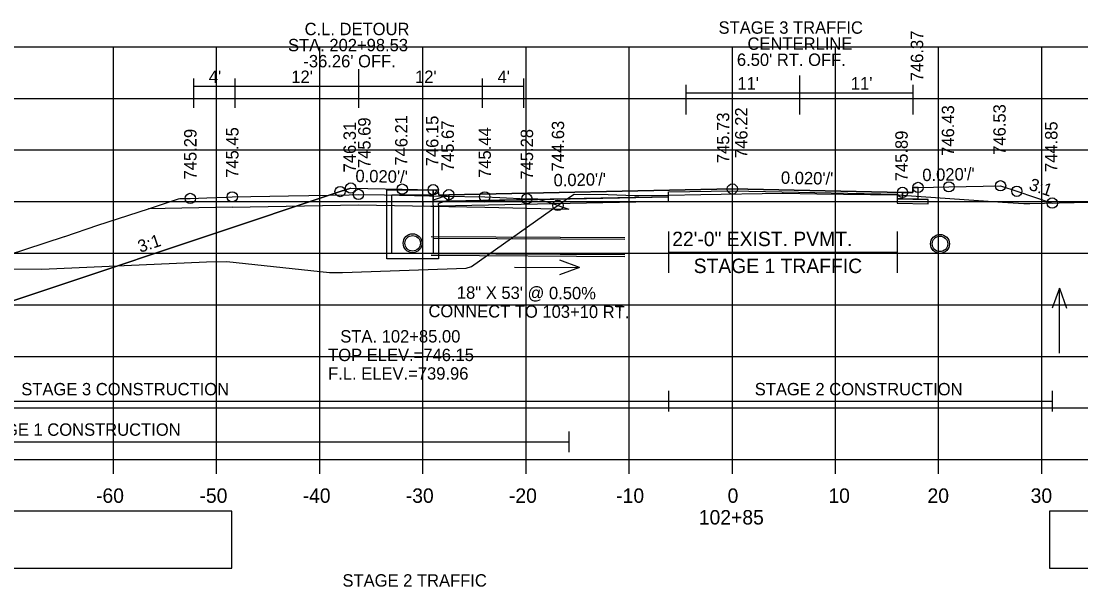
# Model space of a CAD drawing. Extents: x 1202951 to 1376887, y 378065 to 728038.
# Drawn here: x 1376515.7 to 1376618.5, y 378682.8 to 378737.6 of the extents above; entities that cross this region are included whole.
import ezdxf

# ---------------------------------------------------------------- set-up
doc = ezdxf.new("R2010")
doc.units = 0
for name, color, linetype in [('Default', 7, 'Continuous'), ('R_Alt Surface', 7, 'Continuous'), ('R_Axis', 7, 'Continuous'), ('R_Axis Annot', 7, 'Continuous'), ('R_Detour', 7, 'Continuous'), ('R_Detour Annot', 7, 'Continuous'), ('R_Dimension', 7, 'Continuous'), ('R_Exist Surface', 7, 'Continuous'), ('R_Fin Surface', 7, 'Continuous'), ('R_Grid', 7, 'Continuous'), ('R_MOT', 7, 'Continuous'), ('R_No Plot', 7, 'Continuous'), ('R_Proposed Const Limits', 7, 'Continuous'), ('R_Water', 7, 'Continuous'), ('R_Water Annot', 7, 'Continuous'), ('R_Xsect Elev', 7, 'Continuous'), ('R_Xsect Slope', 7, 'Continuous')]:
    doc.layers.add(name, color=color, linetype=linetype)

# ---------------------------------------------------------------- blocks, each defined once
blk = doc.blocks.new('FLOW ARROW')
at = {"layer": 'R_Water Annot'}
for p, q in [((-12.57, 0), (0, 0)), ((0, 0), (-3.85, 1.4)), ((0, 0), (-3.85, -1.4))]:
    blk.add_line(p, q, dxfattribs=at)

msp = doc.modelspace()

# ---------------------------------------------------------------- linework, layer by layer
at = {"layer": 'Default'}
msp.add_lwpolyline([(1376547.67, 378721.46), (1376546.64, 378721.12), (1376546.64, 378721.12), (1376507.16, 378707.95)], dxfattribs=at)
for points in [[(1376602.67, 378721.52), (1376602.18, 378721.52), (1376602.17, 378721.02), (1376601.17, 378721.04), (1376601.17, 378720.41), (1376602.67, 378720.38)], [(1376555.67, 378721.3), (1376556.16, 378721.3), (1376556.17, 378720.8), (1376557.17, 378720.82), (1376557.17, 378720.19), (1376555.67, 378720.16)]]:
    msp.add_lwpolyline(points, close=True, dxfattribs=at)
at = {"layer": 'R_Alt Surface'}
for p, q in [((1376554.67, 378720.14), (1376578.47, 378720.62)), ((1376600.64, 378720.42), (1376603.67, 378720.36)), ((1376554.67, 378720.05), (1376554.67, 378720.1))]:
    msp.add_line(p, q, dxfattribs=at)
msp.add_lwpolyline([(1376555.67, 378721.3), (1376555.67, 378720.16), (1376557.17, 378720.19), (1376578.47, 378720.62), (1376578.47, 378721.08), (1376584.67, 378721.2), (1376600.64, 378720.88), (1376600.64, 378720.42), (1376601.17, 378720.41), (1376602.67, 378720.38), (1376602.67, 378721.52)], dxfattribs=at)
for points in [[(1376557.17, 378720.19), (1376555.67, 378720.16), (1376554.67, 378720.14), (1376554.67, 378719.72), (1376578.47, 378720.2), (1376578.47, 378720.62)], [(1376557.17, 378720.82), (1376557.17, 378720.19), (1376578.47, 378720.62), (1376578.47, 378721.08), (1376584.67, 378721.2), (1376600.64, 378720.88), (1376600.64, 378720.42), (1376601.17, 378720.41), (1376601.17, 378721.04), (1376601.17, 378721.04), (1376584.67, 378721.37), (1376557.17, 378720.82)], [(1376603.67, 378720.36), (1376602.67, 378720.38), (1376601.17, 378720.41), (1376600.64, 378720.42), (1376600.64, 378720), (1376603.67, 378719.94)], [(1376434.67, 378684.63), (1376536.14, 378684.63), (1376536.14, 378690.15), (1376434.67, 378690.15)], [(1376615.43, 378684.63), (1376726.14, 378684.63), (1376726.14, 378690.15), (1376615.43, 378690.15)]]:
    msp.add_lwpolyline(points, close=True, dxfattribs=at)
at = {"layer": 'R_Axis'}
for p, q in [((1376434.67, 378695.15), (1376734.67, 378695.15)), ((1376524.67, 378693.75), (1376524.67, 378695.15)), ((1376534.67, 378693.75), (1376534.67, 378695.15)), ((1376544.67, 378693.75), (1376544.67, 378695.15)), ((1376554.67, 378693.75), (1376554.67, 378695.15)), ((1376564.67, 378693.75), (1376564.67, 378695.15)), ((1376574.67, 378693.75), (1376574.67, 378695.15)), ((1376584.67, 378693.75), (1376584.67, 378695.15)), ((1376594.67, 378693.75), (1376594.67, 378695.15)), ((1376604.67, 378693.75), (1376604.67, 378695.15)), ((1376614.67, 378693.75), (1376614.67, 378695.15))]:
    msp.add_line(p, q, dxfattribs=at)
at = {"layer": 'R_Detour'}
for p, q in [((1376548.42, 378733), (1376548.42, 378729.25)), ((1376532.42, 378732.09), (1376532.42, 378729.25)), ((1376536.42, 378732.09), (1376536.42, 378729.25)), ((1376548.42, 378732.09), (1376548.42, 378729.25)), ((1376560.42, 378732.09), (1376560.42, 378729.25)), ((1376564.42, 378732.09), (1376564.42, 378729.25)), ((1376532.42, 378731.34), (1376536.42, 378731.34)), ((1376536.42, 378731.34), (1376548.42, 378731.34)), ((1376548.42, 378731.34), (1376560.42, 378731.34)), ((1376560.42, 378731.34), (1376564.42, 378731.34))]:
    msp.add_line(p, q, dxfattribs=at)
for points in [[(1376499.67, 378710.13), (1376518.05, 378716.16), (1376519.92, 378716.78), (1376519.94, 378716.78), (1376523.16, 378717.85), (1376528.05, 378719.45), (1376530.97, 378720.41), (1376531.1, 378720.45), (1376531.14, 378720.45), (1376531.89, 378720.45), (1376532.12, 378720.45), (1376533.71, 378720.51), (1376535.65, 378720.59), (1376536.19, 378720.61), (1376541.64, 378720.71), (1376547.52, 378720.82), (1376548.42, 378720.84), (1376550.96, 378720.79), (1376556.75, 378720.67), (1376560.66, 378720.6), (1376562.13, 378720.54), (1376564.75, 378720.43), (1376565.62, 378720.43), (1376565.77, 378720.43), (1376567.72, 378719.79), (1376567.76, 378719.78), (1376567.96, 378719.72), (1376568.83, 378719.43)], [(1376536.19, 378719.61), (1376528.05, 378719.45)], [(1376536.19, 378719.61), (1376548.42, 378719.84), (1376560.66, 378719.6)], [(1376560.66, 378719.6), (1376568.83, 378719.43)]]:
    msp.add_lwpolyline(points, dxfattribs=at)
at = {"layer": 'R_Dimension'}
for points in [[(1376578.47, 378701.8), (1376578.47, 378699.8)], [(1376615.69, 378701.8), (1376615.69, 378699.8)], [(1376473.46, 378700.8), (1376578.47, 378700.8)], [(1376578.47, 378700.8), (1376615.69, 378700.8)], [(1376568.83, 378697.87), (1376568.83, 378695.87)], [(1376473.46, 378696.87), (1376568.83, 378696.87)]]:
    msp.add_lwpolyline(points, dxfattribs=at)
at = {"layer": 'R_Exist Surface'}
for p, q in [((1376555.47, 378716.78), (1376574.25, 378716.68)), ((1376555.47, 378714.95), (1376574.25, 378714.84))]:
    msp.add_line(p, q, dxfattribs=at)
msp.add_lwpolyline([(1376514.06, 378713.62), (1376517.74, 378713.61), (1376533.68, 378714.32), (1376535.67, 378714.35), (1376545.62, 378713.27), (1376546.86, 378713.26), (1376558.85, 378713.69), (1376559.39, 378713.86), (1376568.69, 378720.44), (1376569.34, 378720.88), (1376572.64, 378720.85), (1376575.19, 378720.73), (1376575.59, 378720.74), (1376578.47, 378720.78), (1376581.61, 378720.84), (1376589.54, 378720.96), (1376589.59, 378720.96), (1376592.86, 378720.9), (1376600.64, 378720.8), (1376610.86, 378720.09), (1376612.94, 378719.95), (1376613.51, 378719.96), (1376626.38, 378720.26)], dxfattribs=at)
for centre in [(1376553.67, 378716.11), (1376604.8, 378716.05)]:
    msp.add_circle(centre, 0.917, dxfattribs=at)
at = {"layer": 'R_Fin Surface'}
for p, q in [((1376578.47, 378717.24), (1376578.47, 378713.24)), ((1376578.47, 378717.24), (1376578.47, 378713.24)), ((1376600.64, 378717.24), (1376600.64, 378713.24)), ((1376578.47, 378715.24), (1376600.64, 378715.24)), ((1376578.47, 378715.24), (1376600.4, 378715.24))]:
    msp.add_line(p, q, dxfattribs=at)
for points in [[(1376488.87, 378714.05), (1376507.16, 378707.95), (1376546.64, 378721.12), (1376547.67, 378721.46), (1376552.67, 378721.36), (1376555.67, 378721.3), (1376556.16, 378721.3), (1376556.17, 378720.8), (1376557.17, 378720.82), (1376584.67, 378721.37), (1376601.17, 378721.04), (1376602.17, 378721.02), (1376602.18, 378721.52), (1376602.67, 378721.52), (1376605.67, 378721.58), (1376610.67, 378721.68), (1376612.25, 378721.15), (1376615.69, 378720.01)], [(1376547.67, 378721.46), (1376552.67, 378721.36), (1376555.67, 378721.3), (1376556.16, 378721.3), (1376556.17, 378720.8), (1376557.17, 378720.82), (1376557.17, 378720.82), (1376584.67, 378721.37), (1376601.17, 378721.04), (1376601.17, 378721.04), (1376602.17, 378721.02), (1376602.18, 378721.52), (1376602.67, 378721.52), (1376605.67, 378721.58), (1376610.67, 378721.68)]]:
    msp.add_lwpolyline(points, dxfattribs=at)
at = {"layer": 'R_Grid'}
for p, q in [((1376434.67, 378735.15), (1376734.67, 378735.15)), ((1376524.67, 378695.15), (1376524.67, 378735.15)), ((1376534.67, 378695.15), (1376534.67, 378735.15)), ((1376544.67, 378695.15), (1376544.67, 378735.15)), ((1376554.67, 378695.15), (1376554.67, 378735.15)), ((1376564.67, 378695.15), (1376564.67, 378735.15)), ((1376574.67, 378695.15), (1376574.67, 378735.15)), ((1376584.67, 378695.15), (1376584.67, 378735.15)), ((1376594.67, 378695.15), (1376594.67, 378735.15)), ((1376604.67, 378695.15), (1376604.67, 378735.15)), ((1376614.67, 378695.15), (1376614.67, 378735.15)), ((1376434.67, 378730.15), (1376734.67, 378730.15)), ((1376434.67, 378725.15), (1376734.67, 378725.15)), ((1376434.67, 378720.15), (1376734.67, 378720.15)), ((1376434.67, 378715.15), (1376734.67, 378715.15)), ((1376434.67, 378710.15), (1376734.67, 378710.15)), ((1376434.67, 378705.15), (1376734.67, 378705.15)), ((1376434.67, 378700.15), (1376734.67, 378700.15)), ((1376434.67, 378695.15), (1376734.67, 378695.15))]:
    msp.add_line(p, q, dxfattribs=at)
at = {"layer": 'R_MOT'}
for p, q in [((1376591.17, 378732.36), (1376591.17, 378728.6)), ((1376580.17, 378731.45), (1376580.17, 378728.6)), ((1376580.17, 378730.7), (1376591.17, 378730.7)), ((1376591.17, 378730.7), (1376602.17, 378730.7)), ((1376602.17, 378731.45), (1376602.17, 378728.6))]:
    msp.add_line(p, q, dxfattribs=at)
at = {"layer": 'R_No Plot'}
for centre in [(1376546.64, 378721.12), (1376547.67, 378721.46), (1376547.67, 378721.46), (1376552.67, 378721.36), (1376552.67, 378721.36), (1376555.67, 378721.3), (1376555.67, 378721.3), (1376584.67, 378721.37), (1376584.67, 378721.37), (1376601.17, 378721.04), (1376601.17, 378721.04), (1376602.67, 378721.52), (1376602.67, 378721.52), (1376605.67, 378721.58), (1376605.67, 378721.58), (1376610.67, 378721.68), (1376610.67, 378721.68), (1376612.25, 378721.15), (1376532.12, 378720.45), (1376536.19, 378720.61), (1376548.42, 378720.84), (1376557.17, 378720.82), (1376557.17, 378720.82), (1376560.66, 378720.6), (1376564.75, 378720.43), (1376615.69, 378720.01), (1376615.69, 378720.01), (1376567.76, 378719.78), (1376567.76, 378719.78), (1376567.76, 378719.78)]:
    msp.add_circle(centre, 0.5, dxfattribs=at)
at = {"layer": 'R_Proposed Const Limits'}
msp.add_lwpolyline([(1376610.67, 378721.68), (1376612.25, 378721.15), (1376612.25, 378721.15), (1376615.69, 378720.01)], dxfattribs=at)
at = {"layer": 'R_Water'}
for p, q in [((1376551.17, 378721.3), (1376555.92, 378721.3)), ((1376551.17, 378719.8), (1376551.17, 378721.3)), ((1376551.67, 378719.8), (1376551.67, 378720.8)), ((1376551.67, 378720.8), (1376555.67, 378720.8)), ((1376556, 378721.14), (1376555.67, 378720.8)), ((1376557.17, 378720.82), (1376555.67, 378720.3)), ((1376556, 378721.14), (1376555.92, 378721.3)), ((1376555.67, 378719.8), (1376555.67, 378720.3)), ((1376557.17, 378720.3), (1376556.17, 378719.95)), ((1376556.17, 378719.8), (1376556.17, 378719.95)), ((1376555.67, 378716.61), (1376574.25, 378716.51)), ((1376555.47, 378715.11), (1376574.25, 378715.01))]:
    msp.add_line(p, q, dxfattribs=at)
for points in [[(1376557.17, 378720.3), (1376557.17, 378720.82)], [(1376556.17, 378719.8), (1376556.17, 378714.61), (1376553.67, 378714.61), (1376551.17, 378714.61), (1376551.17, 378719.8)], [(1376555.67, 378719.8), (1376555.67, 378715.11), (1376553.67, 378715.11), (1376551.67, 378715.11), (1376551.67, 378719.8)]]:
    msp.add_lwpolyline(points, dxfattribs=at)
for centre in [(1376553.67, 378716.11), (1376604.8, 378716.05)]:
    msp.add_circle(centre, 0.75, dxfattribs=at)
at = {"layer": 'R_Water Annot'}
for p, q in [((1376616.38, 378711.76), (1376615.68, 378709.83)), ((1376616.38, 378705.47), (1376616.38, 378711.76)), ((1376616.38, 378711.76), (1376617.08, 378709.83))]:
    msp.add_line(p, q, dxfattribs=at)
at = {"layer": 'R_Xsect Elev'}
msp.add_line((1376584.67, 378720.88), (1376584.67, 378730.28), dxfattribs=at)

# ---------------------------------------------------------------- block references
at = {"layer": 'R_Fin Surface', "xscale": 0.49999999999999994, "yscale": 0.49999999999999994, "rotation": -0.31884375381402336}
msp.add_blockref('FLOW ARROW', (1376569.85, 378713.75), dxfattribs=at)

# ---------------------------------------------------------------- texts
at = {"layer": 'R_Axis Annot'}
for s, p in [('22\'-0" EXIST. PVMT.', (1376578.84, 378715.83)), ('STAGE 1 TRAFFIC', (1376580.92, 378713.22)), ('-60', (1376522.98, 378690.95)), ('-50', (1376533.01, 378690.95)), ('-40', (1376543.01, 378690.95)), ('-30', (1376553.01, 378690.95)), ('-20', (1376563.01, 378690.95)), ('-10', (1376573.41, 378690.95)), ('0', (1376584.21, 378690.95)), ('10', (1376593.98, 378690.95)), ('20', (1376603.59, 378690.95)), ('30', (1376613.59, 378690.95)), ('102+85', (1376581.42, 378688.85))]:
    msp.add_text(s, height=1.4, dxfattribs=at).set_placement(p)
at = {"layer": 'R_Detour'}
for s, p in [('C.L. DETOUR', (1376543.2, 378736.28)), ('STA. 202+98.53', (1376541.59, 378734.72)), ("-36.26' OFF.", (1376543.08, 378733.16)), ("4'", (1376533.91, 378731.65)), ("12'", (1376541.91, 378731.65)), ("12'", (1376553.91, 378731.65)), ("4'", (1376561.91, 378731.65)), ('STAGE 2 TRAFFIC', (1376546.87, 378682.83))]:
    msp.add_text(s, height=1.2, dxfattribs=at).set_placement(p)
at = {"layer": 'R_Detour Annot'}
for s, p in [('745.69', (1376549.59, 378723.4)), ('744.63', (1376568.36, 378723.07)), ('745.29', (1376532.72, 378722.29)), ('745.45', (1376536.79, 378722.45)), ('745.44', (1376561.26, 378722.44)), ('745.28', (1376565.35, 378722.28))]:
    msp.add_text(s, height=1.2, rotation=90, dxfattribs=at).set_placement(p)
at = {"layer": 'R_Dimension'}
for s, p in [('STAGE 3 CONSTRUCTION', (1376515.73, 378701.37)), ('STAGE 2 CONSTRUCTION', (1376586.84, 378701.37)), ('STAGE 1 CONSTRUCTION', (1376511.03, 378697.45))]:
    msp.add_text(s, height=1.2, dxfattribs=at).set_placement(p)
at = {"layer": 'R_MOT'}
for s, p in [('STAGE 3 TRAFFIC ', (1376583.33, 378736.42)), ('CENTERLINE', (1376586.14, 378734.86)), ("6.50' RT. OFF.", (1376585.11, 378733.3)), ("11'", (1376585.16, 378731.01)), ("11'", (1376596.16, 378731.01))]:
    msp.add_text(s, height=1.2, dxfattribs=at).set_placement(p)
at = {"layer": 'R_Water Annot'}
for s, p in [('18" X 53\' @ 0.50%', (1376557.96, 378710.74)), ('CONNECT TO 103+10 RT. ', (1376555.2, 378708.95))]:
    msp.add_text(s, height=1.2, rotation=359.6812, dxfattribs=at).set_placement(p)
for s, p in [('STA. 102+85.00', (1376546.66, 378706.49)), ('TOP ELEV.=746.15', (1376545.48, 378704.69)), ('F.L. ELEV.=739.96', (1376545.48, 378702.89))]:
    msp.add_text(s, height=1.2, dxfattribs=at).set_placement(p)
at = {"layer": 'R_Xsect Elev'}
for s, p in [('746.37', (1376603.17, 378731.81)), ('745.73', (1376584.37, 378723.88)), ('746.22', (1376586.13, 378724.37)), ('746.43', (1376606.17, 378724.58)), ('746.43', (1376606.17, 378724.58)), ('746.53', (1376611.17, 378724.68)), ('746.53', (1376611.17, 378724.68)), ('746.31', (1376548.17, 378722.98)), ('746.21', (1376553.17, 378723.63)), ('746.15', (1376556.17, 378723.57)), ('745.67', (1376557.67, 378723.09)), ('744.85', (1376616.19, 378723.01)), ('744.85', (1376616.19, 378723.01)), ('745.89', (1376601.67, 378722.12))]:
    msp.add_text(s, height=1.2, rotation=90, dxfattribs=at).set_placement(p)
at = {"layer": 'R_Xsect Slope'}
for s, rotation, p in [("0.020'/'", 358.8542, (1376548.12, 378722.05)), ("0.020'/'", 1.1458, (1376567.35, 378721.62)), ("0.020'/'", 358.8542, (1376589.37, 378721.88)), ("0.020'/'", 1.1458, (1376603.1, 378722.13)), ('3:1', 341.5651, (1376613.34, 378721.32)), ('3:1', 18.4349, (1376527.26, 378715.18))]:
    msp.add_text(s, height=1.2, rotation=rotation, dxfattribs=at).set_placement(p)

doc.saveas('drawing.dxf')
